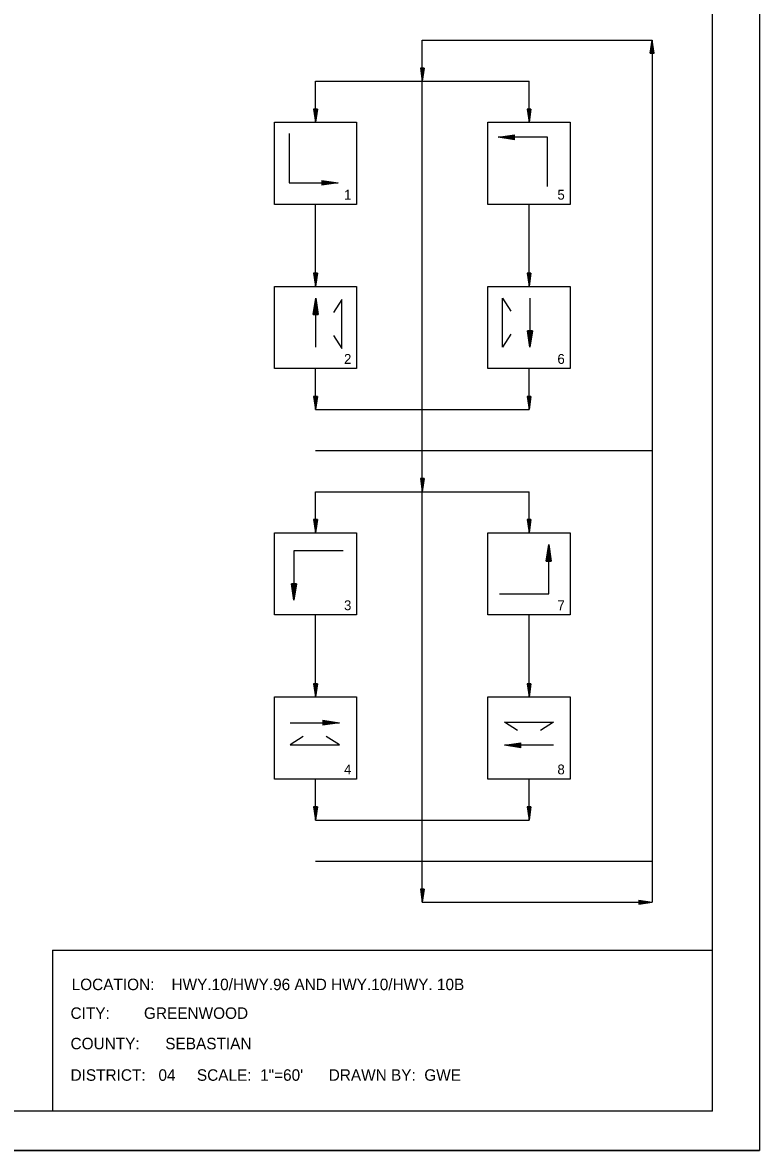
# Model space of a CAD drawing. Extents: x 641001 to 642001, y 326365 to 327005.
# Drawn here: x 641776.9 to 642001.4, y 326365 to 326708.5 of the extents above; entities that cross this region are included whole.
import ezdxf

# ---------------------------------------------------------------- set-up
doc = ezdxf.new("R2010")
doc.units = 0
for name, color, linetype in [('R_Border', 7, 'Continuous'), ('R_Draft', 7, 'Continuous'), ('R_No Plot', 7, 'Continuous'), ('T_Drafting', 7, 'Continuous'), ('T_Notes', 7, 'Continuous')]:
    doc.layers.add(name, color=color, linetype=linetype)

msp = doc.modelspace()

# ---------------------------------------------------------------- linework, layer by layer
at = {"layer": 'R_Border'}
for q in [(641987.11, 326993.34), (641038.57, 326376.96)]:
    msp.add_line((641987.11, 326376.96), q, dxfattribs=at)
at = {"layer": 'R_Draft'}
for p, q in [((641968.07, 326699.11), (641968.67, 326703.11)), ((641968.17, 326699.11), (641968.67, 326702.44)), ((641968.28, 326699.11), (641968.67, 326701.75)), ((641968.38, 326699.11), (641968.67, 326701.09)), ((641969.27, 326699.11), (641968.67, 326703.11)), ((641969.17, 326699.11), (641968.67, 326702.44)), ((641969.07, 326699.11), (641968.67, 326701.75)), ((641968.97, 326699.11), (641968.67, 326701.09)), ((641968.07, 326699.11), (641969.27, 326699.11)), ((641968.48, 326699.11), (641968.67, 326700.41)), ((641968.58, 326699.11), (641968.67, 326699.74)), ((641968.87, 326699.11), (641968.67, 326700.41)), ((641968.77, 326699.11), (641968.67, 326699.74)), ((641898.07, 326694.61), (641898.67, 326690.61)), ((641899.27, 326694.61), (641898.07, 326694.61)), ((641898.17, 326694.61), (641898.67, 326691.28)), ((641898.28, 326694.61), (641898.67, 326691.97)), ((641898.38, 326694.61), (641898.67, 326692.63)), ((641898.48, 326694.61), (641898.67, 326693.31)), ((641898.58, 326694.61), (641898.67, 326693.98)), ((641899.27, 326694.61), (641898.67, 326690.61)), ((641898.87, 326694.61), (641898.67, 326693.31)), ((641899.07, 326694.61), (641898.67, 326691.97)), ((641899.17, 326694.61), (641898.67, 326691.28)), ((641898.97, 326694.61), (641898.67, 326692.63)), ((641898.77, 326694.61), (641898.67, 326693.98)), ((641865.57, 326682.11), (641866.17, 326678.11)), ((641866.77, 326682.11), (641865.57, 326682.11)), ((641865.67, 326682.11), (641866.17, 326678.78)), ((641865.78, 326682.11), (641866.17, 326679.47)), ((641865.88, 326682.11), (641866.17, 326680.13)), ((641865.98, 326682.11), (641866.17, 326680.81)), ((641866.08, 326682.11), (641866.17, 326681.48)), ((641866.77, 326682.11), (641866.17, 326678.11)), ((641866.37, 326682.11), (641866.17, 326680.81)), ((641866.57, 326682.11), (641866.17, 326679.47)), ((641866.67, 326682.11), (641866.17, 326678.78)), ((641866.47, 326682.11), (641866.17, 326680.13)), ((641866.27, 326682.11), (641866.17, 326681.48)), ((641930.57, 326682.11), (641931.17, 326678.11)), ((641931.77, 326682.11), (641930.57, 326682.11)), ((641930.67, 326682.11), (641931.17, 326678.78)), ((641930.78, 326682.11), (641931.17, 326679.47)), ((641930.88, 326682.11), (641931.17, 326680.13)), ((641930.98, 326682.11), (641931.17, 326680.81)), ((641931.08, 326682.11), (641931.17, 326681.48)), ((641931.77, 326682.11), (641931.17, 326678.11)), ((641931.37, 326682.11), (641931.17, 326680.81)), ((641931.57, 326682.11), (641931.17, 326679.47)), ((641931.67, 326682.11), (641931.17, 326678.78)), ((641931.47, 326682.11), (641931.17, 326680.13)), ((641931.27, 326682.11), (641931.17, 326681.48)), ((641865.57, 326632.11), (641866.17, 326628.11)), ((641866.77, 326632.11), (641865.57, 326632.11)), ((641865.67, 326632.11), (641866.17, 326628.78)), ((641865.78, 326632.11), (641866.17, 326629.47)), ((641865.88, 326632.11), (641866.17, 326630.13)), ((641865.98, 326632.11), (641866.17, 326630.81)), ((641866.08, 326632.11), (641866.17, 326631.48)), ((641866.77, 326632.11), (641866.17, 326628.11)), ((641866.37, 326632.11), (641866.17, 326630.81)), ((641866.57, 326632.11), (641866.17, 326629.47)), ((641866.67, 326632.11), (641866.17, 326628.78)), ((641866.47, 326632.11), (641866.17, 326630.13)), ((641866.27, 326632.11), (641866.17, 326631.48)), ((641930.57, 326632.11), (641931.17, 326628.11)), ((641931.77, 326632.11), (641930.57, 326632.11)), ((641930.67, 326632.11), (641931.17, 326628.78)), ((641930.78, 326632.11), (641931.17, 326629.47)), ((641930.88, 326632.11), (641931.17, 326630.13)), ((641930.98, 326632.11), (641931.17, 326630.81)), ((641931.08, 326632.11), (641931.17, 326631.48)), ((641931.77, 326632.11), (641931.17, 326628.11)), ((641931.37, 326632.11), (641931.17, 326630.81)), ((641931.57, 326632.11), (641931.17, 326629.47)), ((641931.67, 326632.11), (641931.17, 326628.78)), ((641931.47, 326632.11), (641931.17, 326630.13)), ((641931.27, 326632.11), (641931.17, 326631.48)), ((641865.57, 326594.61), (641866.17, 326590.61)), ((641866.77, 326594.61), (641865.57, 326594.61)), ((641865.67, 326594.61), (641866.17, 326591.28)), ((641865.78, 326594.61), (641866.17, 326591.97)), ((641865.88, 326594.61), (641866.17, 326592.63)), ((641865.98, 326594.61), (641866.17, 326593.31)), ((641866.08, 326594.61), (641866.17, 326593.98)), ((641866.77, 326594.61), (641866.17, 326590.61)), ((641866.37, 326594.61), (641866.17, 326593.31)), ((641866.57, 326594.61), (641866.17, 326591.97)), ((641866.67, 326594.61), (641866.17, 326591.28)), ((641866.47, 326594.61), (641866.17, 326592.63)), ((641866.27, 326594.61), (641866.17, 326593.98)), ((641930.57, 326594.61), (641931.17, 326590.61)), ((641931.77, 326594.61), (641930.57, 326594.61)), ((641930.67, 326594.61), (641931.17, 326591.28)), ((641930.78, 326594.61), (641931.17, 326591.97)), ((641930.88, 326594.61), (641931.17, 326592.63)), ((641930.98, 326594.61), (641931.17, 326593.31)), ((641931.08, 326594.61), (641931.17, 326593.98)), ((641931.77, 326594.61), (641931.17, 326590.61)), ((641931.37, 326594.61), (641931.17, 326593.31)), ((641931.57, 326594.61), (641931.17, 326591.97)), ((641931.67, 326594.61), (641931.17, 326591.28)), ((641931.47, 326594.61), (641931.17, 326592.63)), ((641931.27, 326594.61), (641931.17, 326593.98)), ((641898.07, 326569.61), (641898.67, 326565.61)), ((641899.27, 326569.61), (641898.07, 326569.61)), ((641898.17, 326569.61), (641898.67, 326566.28)), ((641898.28, 326569.61), (641898.67, 326566.97)), ((641898.38, 326569.61), (641898.67, 326567.63)), ((641898.48, 326569.61), (641898.67, 326568.31)), ((641898.58, 326569.61), (641898.67, 326568.98)), ((641899.27, 326569.61), (641898.67, 326565.61)), ((641898.87, 326569.61), (641898.67, 326568.31)), ((641899.07, 326569.61), (641898.67, 326566.97)), ((641899.17, 326569.61), (641898.67, 326566.28)), ((641898.97, 326569.61), (641898.67, 326567.63)), ((641898.77, 326569.61), (641898.67, 326568.98)), ((641865.57, 326557.11), (641866.17, 326553.11)), ((641866.77, 326557.11), (641865.57, 326557.11)), ((641865.67, 326557.11), (641866.17, 326553.78)), ((641865.78, 326557.11), (641866.17, 326554.47)), ((641865.88, 326557.11), (641866.17, 326555.13)), ((641865.98, 326557.11), (641866.17, 326555.81)), ((641866.08, 326557.11), (641866.17, 326556.48)), ((641866.77, 326557.11), (641866.17, 326553.11)), ((641866.37, 326557.11), (641866.17, 326555.81)), ((641866.57, 326557.11), (641866.17, 326554.47)), ((641866.67, 326557.11), (641866.17, 326553.78)), ((641866.47, 326557.11), (641866.17, 326555.13)), ((641866.27, 326557.11), (641866.17, 326556.48)), ((641930.57, 326557.11), (641931.17, 326553.11)), ((641931.77, 326557.11), (641930.57, 326557.11)), ((641930.67, 326557.11), (641931.17, 326553.78)), ((641930.78, 326557.11), (641931.17, 326554.47)), ((641930.88, 326557.11), (641931.17, 326555.13)), ((641930.98, 326557.11), (641931.17, 326555.81)), ((641931.08, 326557.11), (641931.17, 326556.48)), ((641931.77, 326557.11), (641931.17, 326553.11)), ((641931.37, 326557.11), (641931.17, 326555.81)), ((641931.57, 326557.11), (641931.17, 326554.47)), ((641931.67, 326557.11), (641931.17, 326553.78)), ((641931.47, 326557.11), (641931.17, 326555.13)), ((641931.27, 326557.11), (641931.17, 326556.48)), ((641865.57, 326507.11), (641866.17, 326503.11)), ((641866.77, 326507.11), (641865.57, 326507.11)), ((641865.67, 326507.11), (641866.17, 326503.78)), ((641865.78, 326507.11), (641866.17, 326504.47)), ((641865.88, 326507.11), (641866.17, 326505.13)), ((641865.98, 326507.11), (641866.17, 326505.81)), ((641866.08, 326507.11), (641866.17, 326506.48)), ((641866.77, 326507.11), (641866.17, 326503.11)), ((641866.37, 326507.11), (641866.17, 326505.81)), ((641866.57, 326507.11), (641866.17, 326504.47)), ((641866.67, 326507.11), (641866.17, 326503.78)), ((641866.47, 326507.11), (641866.17, 326505.13)), ((641866.27, 326507.11), (641866.17, 326506.48)), ((641930.57, 326507.11), (641931.17, 326503.11)), ((641931.77, 326507.11), (641930.57, 326507.11)), ((641930.67, 326507.11), (641931.17, 326503.78)), ((641930.78, 326507.11), (641931.17, 326504.47)), ((641930.88, 326507.11), (641931.17, 326505.13)), ((641930.98, 326507.11), (641931.17, 326505.81)), ((641931.08, 326507.11), (641931.17, 326506.48)), ((641931.77, 326507.11), (641931.17, 326503.11)), ((641931.37, 326507.11), (641931.17, 326505.81)), ((641931.57, 326507.11), (641931.17, 326504.47)), ((641931.67, 326507.11), (641931.17, 326503.78)), ((641931.47, 326507.11), (641931.17, 326505.13)), ((641931.27, 326507.11), (641931.17, 326506.48)), ((641865.57, 326469.61), (641866.17, 326465.61)), ((641866.77, 326469.61), (641865.57, 326469.61)), ((641865.67, 326469.61), (641866.17, 326466.28)), ((641865.78, 326469.61), (641866.17, 326466.97)), ((641865.88, 326469.61), (641866.17, 326467.63)), ((641865.98, 326469.61), (641866.17, 326468.31)), ((641866.08, 326469.61), (641866.17, 326468.98)), ((641866.77, 326469.61), (641866.17, 326465.61)), ((641866.37, 326469.61), (641866.17, 326468.31)), ((641866.57, 326469.61), (641866.17, 326466.97)), ((641866.67, 326469.61), (641866.17, 326466.28)), ((641866.47, 326469.61), (641866.17, 326467.63)), ((641866.27, 326469.61), (641866.17, 326468.98)), ((641930.57, 326469.61), (641931.17, 326465.61)), ((641931.77, 326469.61), (641930.57, 326469.61)), ((641930.67, 326469.61), (641931.17, 326466.28)), ((641930.78, 326469.61), (641931.17, 326466.97)), ((641930.88, 326469.61), (641931.17, 326467.63)), ((641930.98, 326469.61), (641931.17, 326468.31)), ((641931.08, 326469.61), (641931.17, 326468.98)), ((641931.77, 326469.61), (641931.17, 326465.61)), ((641931.37, 326469.61), (641931.17, 326468.31)), ((641931.57, 326469.61), (641931.17, 326466.97)), ((641931.67, 326469.61), (641931.17, 326466.28)), ((641931.47, 326469.61), (641931.17, 326467.63)), ((641931.27, 326469.61), (641931.17, 326468.98)), ((641898.07, 326444.61), (641898.67, 326440.61)), ((641899.27, 326444.61), (641898.07, 326444.61)), ((641898.17, 326444.61), (641898.67, 326441.28)), ((641898.28, 326444.61), (641898.67, 326441.97)), ((641898.38, 326444.61), (641898.67, 326442.63)), ((641898.48, 326444.61), (641898.67, 326443.31)), ((641898.58, 326444.61), (641898.67, 326443.98)), ((641899.27, 326444.61), (641898.67, 326440.61)), ((641898.87, 326444.61), (641898.67, 326443.31)), ((641899.07, 326444.61), (641898.67, 326441.97)), ((641899.17, 326444.61), (641898.67, 326441.28)), ((641898.97, 326444.61), (641898.67, 326442.63)), ((641898.77, 326444.61), (641898.67, 326443.98)), ((641964.67, 326441.21), (641968.67, 326440.61)), ((641964.67, 326441.21), (641964.67, 326440.01)), ((641964.67, 326441.11), (641968.01, 326440.61)), ((641964.67, 326441.01), (641967.32, 326440.61)), ((641964.67, 326440.91), (641966.65, 326440.61)), ((641964.67, 326440.8), (641965.97, 326440.61)), ((641964.67, 326440.7), (641965.31, 326440.61)), ((641964.67, 326440.01), (641968.67, 326440.61)), ((641964.67, 326440.41), (641965.97, 326440.61)), ((641964.67, 326440.21), (641967.32, 326440.61)), ((641964.67, 326440.11), (641968.01, 326440.61)), ((641964.67, 326440.31), (641966.65, 326440.61)), ((641964.67, 326440.52), (641965.31, 326440.61))]:
    msp.add_line(p, q, dxfattribs=at)
at = {"layer": 'R_No Plot'}
msp.add_line((641001.36, 326365.02), (642001.36, 326365.02), dxfattribs=at)
msp.add_lwpolyline([(641001.34, 327005.02), (642001.36, 327005.02), (642001.36, 326365.01), (641001.34, 326365.01)], close=True, dxfattribs=at)
at = {"layer": 'T_Drafting'}
for p, q in [((641898.67, 326440.61), (641898.67, 326703.11)), ((641898.67, 326703.11), (641968.67, 326703.11)), ((641968.67, 326703.11), (641968.67, 326440.61)), ((641866.17, 326678.11), (641866.17, 326690.61)), ((641866.17, 326690.61), (641931.17, 326690.61)), ((641931.17, 326678.11), (641931.17, 326690.61)), ((641858.07, 326674.66), (641858.07, 326659.66)), ((641921.79, 326673.54), (641926.79, 326674.29)), ((641936.79, 326673.54), (641921.79, 326673.54)), ((641926.79, 326672.79), (641921.79, 326673.54)), ((641926.79, 326674.16), (641922.62, 326673.54)), ((641922.62, 326673.54), (641926.79, 326672.91)), ((641923.48, 326673.54), (641926.79, 326674.04)), ((641926.79, 326673.04), (641923.48, 326673.54)), ((641926.79, 326673.91), (641924.32, 326673.54)), ((641924.32, 326673.54), (641926.79, 326673.17)), ((641925.16, 326673.54), (641926.79, 326673.78)), ((641926.79, 326673.3), (641925.16, 326673.54)), ((641926.79, 326673.66), (641926, 326673.54)), ((641926, 326673.54), (641926.79, 326673.42)), ((641926.79, 326672.79), (641926.79, 326674.29)), ((641936.79, 326658.54), (641936.79, 326673.54)), ((641858.07, 326659.66), (641873.07, 326659.66)), ((641868.07, 326660.41), (641873.07, 326659.66)), ((641868.07, 326660.41), (641868.07, 326658.91)), ((641872.24, 326659.66), (641868.07, 326660.29)), ((641868.07, 326660.16), (641871.38, 326659.66)), ((641870.54, 326659.66), (641868.07, 326660.03)), ((641868.07, 326659.9), (641869.7, 326659.66)), ((641868.86, 326659.66), (641868.07, 326659.78)), ((641873.07, 326659.66), (641868.07, 326658.91)), ((641868.07, 326659.04), (641872.24, 326659.66)), ((641871.38, 326659.66), (641868.07, 326659.16)), ((641868.07, 326659.29), (641870.54, 326659.66)), ((641869.7, 326659.66), (641868.07, 326659.42)), ((641868.07, 326659.54), (641868.86, 326659.66)), ((641866.17, 326628.11), (641866.17, 326653.11)), ((641931.17, 326628.11), (641931.17, 326653.11)), ((641865.44, 326619.57), (641866.19, 326624.57)), ((641866.19, 326623.74), (641865.57, 326619.57)), ((641865.69, 326619.57), (641866.19, 326622.88)), ((641866.19, 326622.04), (641865.82, 326619.57)), ((641866.19, 326609.57), (641866.19, 326624.57)), ((641866.19, 326624.57), (641866.94, 326619.57)), ((641866.82, 326619.57), (641866.19, 326623.74)), ((641866.19, 326622.88), (641866.69, 326619.57)), ((641866.56, 326619.57), (641866.19, 326622.04)), ((641931.45, 326624.57), (641931.45, 326609.57)), ((641865.44, 326619.57), (641866.94, 326619.57)), ((641865.95, 326619.57), (641866.19, 326621.2)), ((641866.19, 326620.36), (641866.07, 326619.57)), ((641866.19, 326621.2), (641866.44, 326619.57)), ((641866.31, 326619.57), (641866.19, 326620.36)), ((641931.45, 326609.57), (641930.7, 326614.57)), ((641932.2, 326614.57), (641930.7, 326614.57)), ((641930.82, 326614.57), (641931.45, 326610.41)), ((641931.45, 326611.27), (641930.95, 326614.57)), ((641931.08, 326614.57), (641931.45, 326612.1)), ((641931.45, 326612.95), (641931.2, 326614.57)), ((641931.33, 326614.57), (641931.45, 326613.78)), ((641931.45, 326613.78), (641931.57, 326614.57)), ((641931.69, 326614.57), (641931.45, 326612.95)), ((641931.45, 326612.1), (641931.82, 326614.57)), ((641931.95, 326614.57), (641931.45, 326611.27)), ((641931.45, 326610.41), (641932.07, 326614.57)), ((641932.2, 326614.57), (641931.45, 326609.57)), ((641866.17, 326590.61), (641866.17, 326603.11)), ((641931.17, 326590.61), (641931.17, 326603.11)), ((641866.17, 326590.61), (641931.17, 326590.61)), ((641866.17, 326578.11), (641968.67, 326578.11)), ((641866.17, 326565.61), (641931.17, 326565.61)), ((641866.17, 326553.11), (641866.17, 326565.61)), ((641931.17, 326553.11), (641931.17, 326565.61)), ((641874.58, 326547.55), (641859.58, 326547.55)), ((641859.58, 326547.55), (641859.58, 326532.55)), ((641936.41, 326544.49), (641937.16, 326549.49)), ((641937.16, 326548.65), (641936.53, 326544.49)), ((641936.66, 326544.49), (641937.16, 326547.79)), ((641937.16, 326546.96), (641936.79, 326544.49)), ((641937.16, 326534.49), (641937.16, 326549.49)), ((641937.16, 326549.49), (641937.91, 326544.49)), ((641937.78, 326544.49), (641937.16, 326548.65)), ((641937.16, 326547.79), (641937.66, 326544.49)), ((641937.53, 326544.49), (641937.16, 326546.96)), ((641936.41, 326544.49), (641937.91, 326544.49)), ((641936.92, 326544.49), (641937.16, 326546.11)), ((641937.16, 326545.28), (641937.04, 326544.49)), ((641937.16, 326546.11), (641937.4, 326544.49)), ((641937.28, 326544.49), (641937.16, 326545.28)), ((641859.58, 326532.55), (641858.83, 326537.55)), ((641860.33, 326537.55), (641858.83, 326537.55)), ((641858.96, 326537.55), (641859.58, 326533.39)), ((641859.58, 326534.25), (641859.09, 326537.55)), ((641859.21, 326537.55), (641859.58, 326535.08)), ((641859.58, 326535.93), (641859.34, 326537.55)), ((641859.47, 326537.55), (641859.58, 326536.76)), ((641859.58, 326536.76), (641859.7, 326537.55)), ((641859.83, 326537.55), (641859.58, 326535.93)), ((641859.58, 326535.08), (641859.96, 326537.55)), ((641860.08, 326537.55), (641859.58, 326534.25)), ((641859.58, 326533.39), (641860.21, 326537.55)), ((641860.33, 326537.55), (641859.58, 326532.55)), ((641922.16, 326534.49), (641937.16, 326534.49)), ((641866.17, 326503.11), (641866.17, 326528.11)), ((641931.17, 326503.11), (641931.17, 326528.11)), ((641858.41, 326495.25), (641873.41, 326495.25)), ((641868.41, 326496), (641873.41, 326495.25)), ((641868.41, 326496), (641868.41, 326494.5)), ((641872.57, 326495.25), (641868.41, 326495.88)), ((641868.41, 326495.75), (641871.71, 326495.25)), ((641870.88, 326495.25), (641868.41, 326495.62)), ((641868.41, 326495.49), (641870.03, 326495.25)), ((641869.2, 326495.25), (641868.41, 326495.37)), ((641873.41, 326495.25), (641868.41, 326494.5)), ((641868.41, 326494.63), (641872.57, 326495.25)), ((641871.71, 326495.25), (641868.41, 326494.75)), ((641868.41, 326494.88), (641870.88, 326495.25)), ((641870.03, 326495.25), (641868.41, 326495.01)), ((641868.41, 326495.13), (641869.2, 326495.25)), ((641923.66, 326488.38), (641928.66, 326489.13)), ((641938.66, 326488.38), (641923.66, 326488.38)), ((641928.66, 326487.63), (641923.66, 326488.38)), ((641928.66, 326489), (641924.49, 326488.38)), ((641924.49, 326488.38), (641928.66, 326487.75)), ((641925.35, 326488.38), (641928.66, 326488.88)), ((641928.66, 326487.88), (641925.35, 326488.38)), ((641928.66, 326488.75), (641926.19, 326488.38)), ((641926.19, 326488.38), (641928.66, 326488.01)), ((641927.03, 326488.38), (641928.66, 326488.62)), ((641928.66, 326488.14), (641927.03, 326488.38)), ((641928.66, 326488.5), (641927.87, 326488.38)), ((641927.87, 326488.38), (641928.66, 326488.26)), ((641928.66, 326487.63), (641928.66, 326489.13)), ((641866.17, 326465.61), (641866.17, 326478.11)), ((641931.17, 326465.61), (641931.17, 326478.11)), ((641866.17, 326465.61), (641931.17, 326465.61)), ((641866.17, 326453.11), (641968.67, 326453.11)), ((641898.67, 326440.61), (641968.67, 326440.61))]:
    msp.add_line(p, q, dxfattribs=at)
for points in [[(641853.67, 326678.11), (641878.67, 326678.11), (641878.67, 326653.11), (641853.67, 326653.11)], [(641918.67, 326678.11), (641943.67, 326678.11), (641943.67, 326653.11), (641918.67, 326653.11)], [(641853.67, 326628.11), (641878.67, 326628.11), (641878.67, 326603.11), (641853.67, 326603.11)], [(641918.67, 326628.11), (641943.67, 326628.11), (641943.67, 326603.11), (641918.67, 326603.11)], [(641853.67, 326553.11), (641878.67, 326553.11), (641878.67, 326528.11), (641853.67, 326528.11)], [(641918.67, 326553.11), (641943.67, 326553.11), (641943.67, 326528.11), (641918.67, 326528.11)], [(641853.67, 326503.11), (641878.67, 326503.11), (641878.67, 326478.11), (641853.67, 326478.11)], [(641918.67, 326503.11), (641943.67, 326503.11), (641943.67, 326478.11), (641918.67, 326478.11)]]:
    msp.add_lwpolyline(points, close=True, dxfattribs=at)
for points in [[(641871.66, 326613.18), (641874.16, 326609.18), (641874.16, 326624.18), (641871.66, 326620.18)], [(641925.6, 326613.57), (641923.1, 326609.57), (641923.1, 326624.57), (641925.6, 326620.57)], [(641927.66, 326492.89), (641923.66, 326495.39), (641938.66, 326495.39), (641934.66, 326492.89)], [(641862.41, 326491.06), (641858.41, 326488.56), (641873.41, 326488.56), (641869.41, 326491.06)], [(641786.04, 326425.99), (641987.11, 326425.99)], [(641786.04, 326425.99), (641786.04, 326376.96)]]:
    msp.add_lwpolyline(points, dxfattribs=at)

# ---------------------------------------------------------------- texts
for s, height, p in [('LOCATION:    HWY.10/HWY.96 AND HWY.10/HWY. 10B', 3.499, (641791.86, 326413.82)), ('CITY:        GREENWOOD', 3.5, (641791.52, 326405.07)), ('COUNTY:      SEBASTIAN', 3.5, (641791.52, 326395.81)), ('DISTRICT:   04     SCALE:  1"=60\'      DRAWN BY:  GWE', 3.5, (641791.52, 326386.22))]:
    msp.add_text(s, height=height, dxfattribs=at).set_placement(p)
at = {"layer": 'T_Notes'}
for s, p in [('1', (641874.83, 326654.53)), ('5', (641939.83, 326654.53)), ('2', (641874.83, 326604.53)), ('6', (641939.83, 326604.53)), ('3', (641874.83, 326529.53)), ('7', (641939.83, 326529.53)), ('4', (641874.83, 326479.53)), ('8', (641939.83, 326479.53))]:
    msp.add_text(s, height=3, dxfattribs=at).set_placement(p)

doc.saveas('drawing.dxf')
